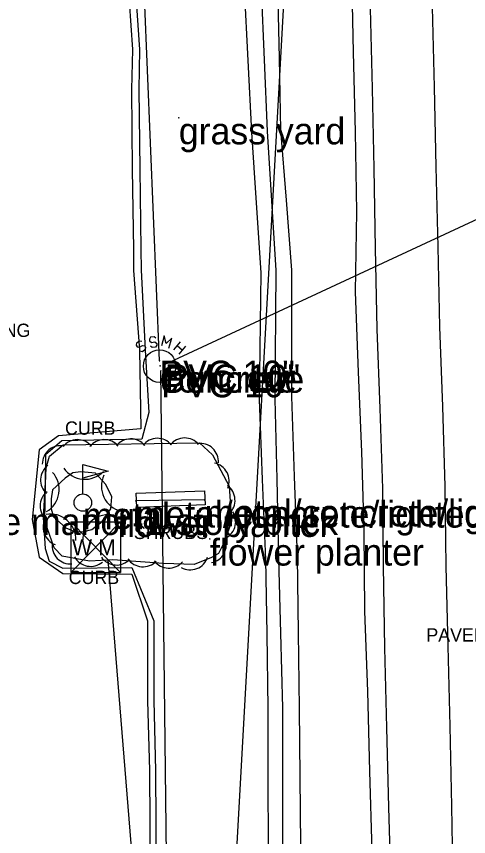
# Model space of a CAD drawing. Extents: x 1802180 to 1804859, y 572524 to 575172.
# Drawn here: x 1803444.8 to 1803529.6, y 574596.9 to 574750.8 of the extents above; entities that cross this region are included whole.
import ezdxf

# ---------------------------------------------------------------- set-up
doc = ezdxf.new("R2010")
doc.units = 0
for name, color, linetype in [('EX_EDGE_PAVEMENT', 7, 'Continuous'), ('EX_SHOULDER', 7, 'Continuous'), ('S_BASELINE', 7, 'Continuous'), ('S_CURB', 7, 'Continuous'), ('S_CURB_ANNOT', 7, 'Continuous'), ('S_DITCHLINE', 7, 'Continuous'), ('S_FLAG_POLE', 7, 'Continuous'), ('S_FLAG_POLE_ANNOT', 7, 'Continuous'), ('S_MANHOLE_ANNOT', 7, 'Continuous'), ('S_MSC_PT_SYM', 7, 'Continuous'), ('S_PARKING', 7, 'Continuous'), ('S_PARKING_ANNOT', 7, 'Continuous'), ('S_PAVEMENT_CROWN', 7, 'Continuous'), ('S_SANITARY_SEWER', 7, 'Continuous'), ('S_SANITARY_SEWER_ANNOT', 7, 'Continuous'), ('S_SHOULDER_ANNOT', 7, 'Continuous'), ('S_SIGN', 7, 'Continuous'), ('S_SIGN_ANNOT', 7, 'Continuous'), ('S_SURVEY_TEXT_ANNOT', 7, 'Continuous'), ('S_TREE', 7, 'Continuous'), ('S_TREE_ANNOT', 7, 'Continuous'), ('S_UTL_PT_SYM', 7, 'Continuous'), ('S_WATER_UTILITIES', 7, 'Continuous')]:
    doc.layers.add(name, color=color, linetype=linetype)

msp = doc.modelspace()

# ---------------------------------------------------------------- linework, layer by layer
at = {"layer": 'EX_EDGE_PAVEMENT'}
msp.add_lwpolyline([(1803511.15, 574752.25), (1803511.51, 574737.25), (1803511.85, 574722.28), (1803512.06, 574707.28), (1803512.41, 574692.1), (1803512.98, 574677.21), (1803513.44, 574662.21), (1803513.59, 574647.61), (1803513.85, 574632.28), (1803514.23, 574617.28), (1803514.59, 574602.41), (1803515.02, 574587.41), (1803515.25, 574572.41), (1803515.5, 574557.21), (1803515.92, 574542.31), (1803516.28, 574527.32), (1803516.63, 574512.39), (1803516.94, 574497.47), (1803517.26, 574482.47), (1803517.51, 574467.47)], dxfattribs=at)
at = {"layer": 'EX_SHOULDER'}
msp.add_lwpolyline([(1803513.3, 574459.21), (1803513.14, 574474.16), (1803512.83, 574489.15), (1803512.51, 574504.15), (1803513.08, 574519.16), (1803512.55, 574534.14), (1803512.14, 574549.14), (1803512, 574564.12), (1803511.96, 574579.17), (1803511.52, 574594.12), (1803511.07, 574609.12), (1803510.69, 574624.12), (1803510.14, 574639.14), (1803510.02, 574654.22), (1803509.58, 574669.09), (1803508.98, 574684.03), (1803508.41, 574699.09), (1803508.62, 574714.13), (1803508.42, 574729.1), (1803508.04, 574744.09), (1803507.71, 574759.1)], dxfattribs=at)
at = {"layer": 'S_BASELINE'}
msp.add_line((1803445.92, 573868.28), (1803500.45, 574852.59), dxfattribs=at)
at = {"layer": 'S_CURB'}
msp.add_lwpolyline([(1803467.27, 574753.7), (1803467.89, 574744.56), (1803467.75, 574737.06), (1803467.92, 574722.11), (1803468.12, 574707.11), (1803468.17, 574703.2), (1803468.95, 574688.18), (1803469.61, 574676.46), (1803468.29, 574671.46), (1803453.29, 574671.14), (1803450.27, 574668.52), (1803450.2, 574663.33), (1803449.82, 574656.78), (1803450.16, 574650.94), (1803450.92, 574648.56), (1803453.5, 574647.22), (1803466.47, 574647.34), (1803470.55, 574637.34), (1803470.57, 574622.37), (1803470.89, 574609.28), (1803470.96, 574599.35), (1803470.98, 574589.91)], dxfattribs=at)
at = {"layer": 'S_DITCHLINE'}
for points in [[(1803490.07, 574794.16), (1803489.66, 574780.03), (1803490.7, 574755.99), (1803491.27, 574742.62), (1803491.83, 574729.26), (1803492.65, 574716.19), (1803493.48, 574703.12), (1803493.27, 574678.93), (1803493.61, 574663.96), (1803493.94, 574648.99), (1803494.34, 574635.02), (1803494.73, 574621.05), (1803494.72, 574607.79), (1803494.71, 574594.54), (1803495.49, 574581.95), (1803496.28, 574569.36), (1803495.67, 574551.97), (1803495.95, 574537.6), (1803495.58, 574518.76), (1803495.69, 574501.1), (1803495.36, 574490.9), (1803494.55, 574477.41), (1803495.42, 574468.77), (1803496.15, 574468.87)], [(1803490.07, 574794.16), (1803491.29, 574793.32), (1803491.77, 574780.2), (1803493.77, 574756.45), (1803494.07, 574742.95), (1803494.36, 574729.45), (1803495.37, 574716.3), (1803496.38, 574703.14), (1803496.39, 574679.47), (1803496.92, 574664.43), (1803497.45, 574649.38), (1803497.65, 574635.15), (1803497.85, 574620.92), (1803497.95, 574608.06), (1803498.05, 574595.2), (1803498.74, 574582.27), (1803499.43, 574569.34), (1803499.04, 574551.94), (1803499.25, 574537.64), (1803498.31, 574518.86), (1803498.17, 574501.26), (1803497.39, 574490.99), (1803496.83, 574477.44), (1803496.15, 574468.87)], [(1803487.53, 574756.11), (1803488.21, 574742.54), (1803488.9, 574728.98), (1803489.77, 574715.83), (1803490.65, 574702.69), (1803490.32, 574678.88), (1803490.92, 574663.88), (1803491.52, 574648.88), (1803491.74, 574634.91), (1803491.96, 574620.93), (1803491.97, 574607.92), (1803491.99, 574594.91), (1803492.03, 574582.33), (1803492.07, 574569.76), (1803492.72, 574552.46), (1803493.14, 574537.68), (1803492.47, 574519.03), (1803493.27, 574501.14), (1803493.74, 574490.94), (1803492.85, 574477.56), (1803494.06, 574470.25), (1803495.42, 574468.77)]]:
    msp.add_lwpolyline(points, dxfattribs=at)
at = {"layer": 'S_FLAG_POLE'}
for p, q in [((1803457.25, 574661.16), (1803457.25, 574666.7)), ((1803457.25, 574666.7), (1803462.01, 574665.43)), ((1803462.01, 574665.43), (1803457.25, 574664.15))]:
    msp.add_line(p, q, dxfattribs=at)
msp.add_circle((1803457.25, 574659.54), 1.63, dxfattribs=at)
at = {"layer": 'S_MSC_PT_SYM'}
for points in [[(1803475.26, 574731.78), (1803475.26, 574731.83), (1803475.26, 574731.78), (1803475.21, 574731.78), (1803475.26, 574731.78), (1803475.26, 574731.73), (1803475.26, 574731.78), (1803475.31, 574731.78)], [(1803467.16, 574659.85), (1803467.16, 574659.9), (1803467.16, 574659.85), (1803467.11, 574659.85), (1803467.16, 574659.85), (1803467.16, 574659.8), (1803467.16, 574659.85), (1803467.21, 574659.85)], [(1803480.08, 574660.09), (1803480.08, 574660.14), (1803480.08, 574660.09), (1803480.03, 574660.09), (1803480.08, 574660.09), (1803480.08, 574660.04), (1803480.08, 574660.09), (1803480.13, 574660.09)], [(1803463.71, 574658.1), (1803463.71, 574658.15), (1803463.71, 574658.1), (1803463.66, 574658.1), (1803463.71, 574658.1), (1803463.71, 574658.05), (1803463.71, 574658.1), (1803463.76, 574658.1)], [(1803481.09, 574652.72), (1803481.09, 574652.77), (1803481.09, 574652.72), (1803481.04, 574652.72), (1803481.09, 574652.72), (1803481.09, 574652.67), (1803481.09, 574652.72), (1803481.14, 574652.72)]]:
    msp.add_lwpolyline(points, dxfattribs=at)
at = {"layer": 'S_PARKING'}
msp.add_lwpolyline([(1803465.97, 574753.62), (1803466.55, 574744.6), (1803466.36, 574737.09), (1803466.52, 574722.09), (1803466.73, 574707.09), (1803466.78, 574703.1), (1803467.85, 574688.16), (1803468.11, 574673.42), (1803452.66, 574672.05), (1803449.03, 574669.45), (1803447.73, 574656.4), (1803449.04, 574649.33), (1803453.47, 574646.26), (1803466.43, 574646.12), (1803469.38, 574637.34), (1803469.4, 574622.34), (1803469.77, 574609.24), (1803469.84, 574599.34), (1803469.86, 574589.91)], dxfattribs=at)
msp.add_lwpolyline([(1803465.97, 574753.62), (1803466.55, 574744.6), (1803466.36, 574737.09), (1803466.52, 574722.09), (1803466.73, 574707.09), (1803466.78, 574703.1), (1803467.85, 574688.16), (1803468.11, 574673.42), (1803452.66, 574672.05), (1803449.03, 574669.45), (1803447.73, 574656.4), (1803449.04, 574649.33), (1803453.47, 574646.26), (1803466.43, 574646.12), (1803469.38, 574637.34), (1803469.4, 574622.34), (1803469.77, 574609.24), (1803469.84, 574599.34), (1803469.86, 574589.91)], dxfattribs=at)
at = {"layer": 'S_PAVEMENT_CROWN'}
msp.add_lwpolyline([(1803522.78, 574752.53), (1803523.15, 574737.54), (1803523.48, 574722.54), (1803523.82, 574707.54), (1803524.16, 574692.55), (1803524.71, 574677.56), (1803525.16, 574662.57), (1803525.35, 574647.57), (1803525.71, 574632.58), (1803526.09, 574617.58), (1803526.43, 574602.58), (1803526.65, 574587.59), (1803526.88, 574572.59), (1803527.34, 574557.6), (1803527.76, 574542.6), (1803528.13, 574527.61), (1803528.41, 574512.61), (1803528.68, 574497.61), (1803528.87, 574482.61), (1803529.05, 574467.61)], dxfattribs=at)
at = {"layer": 'S_SANITARY_SEWER'}
for p, q in [((1803471.62, 574686.18), (1803464.18, 574867.1)), ((1803472.59, 574685.48), (1803580.89, 574735.83)), ((1803467.87, 574689.85), (1803467.33, 574689.46)), ((1803468.3, 574689.77), (1803467.87, 574689.85)), ((1803467.33, 574689.46), (1803467.25, 574689.07)), ((1803467.25, 574689.07), (1803467.44, 574688.8)), ((1803467.44, 574688.8), (1803467.87, 574688.69)), ((1803467.87, 574688.69), (1803468.41, 574689.03)), ((1803468.41, 574689.03), (1803468.88, 574688.96)), ((1803468.88, 574688.96), (1803469.03, 574688.69)), ((1803469.03, 574688.69), (1803468.95, 574688.26)), ((1803474.3, 574688.22), (1803475.54, 574689.69)), ((1803474.96, 574689), (1803475.93, 574688.18)), ((1803476.51, 574688.88), (1803475.27, 574687.41)), ((1803468.41, 574687.87), (1803468.02, 574687.95)), ((1803468.95, 574688.26), (1803468.41, 574687.87)), ((1803476.11, 574323.57), (1803471.91, 574684.3))]:
    msp.add_line(p, q, dxfattribs=at)
for points in [[(1803470.97, 574690.39), (1803470.62, 574690.66), (1803469.96, 574690.58), (1803469.73, 574690.24), (1803469.77, 574689.93), (1803470.12, 574689.62), (1803470.74, 574689.73), (1803471.12, 574689.42), (1803471.16, 574689.11), (1803470.89, 574688.72), (1803470.27, 574688.65), (1803469.92, 574688.92)], [(1803473.41, 574688.53), (1803473.95, 574690.39), (1803472.91, 574689.38), (1803472.52, 574690.82), (1803471.98, 574688.96)]]:
    msp.add_lwpolyline(points, dxfattribs=at)
msp.add_circle((1803471.65, 574685.16), 3.05, dxfattribs=at)
at = {"layer": 'S_SIGN'}
msp.add_line((1803480.08, 574660.09), (1803467.16, 574659.85), dxfattribs=at)
msp.add_lwpolyline([(1803467.24, 574661.29), (1803480.1, 574661.75), (1803480.21, 574659.14), (1803467.39, 574658.63), (1803467.24, 574661.29)], dxfattribs=at)
at = {"layer": 'S_TREE'}
for points in [[(1803453.55, 574670.4), (1803479.13, 574670.77), (1803481.56, 574668.5), (1803484.71, 574662.64), (1803485.12, 574656.05), (1803483.85, 574652.17), (1803483.21, 574651.01), (1803482.67, 574650.02), (1803481.38, 574649.23), (1803478.16, 574647.96), (1803472.38, 574648.13), (1803462.87, 574648.83), (1803458.48, 574648.54), (1803453.35, 574649.5), (1803451.84, 574651.05), (1803450.12, 574656.07), (1803450.22, 574663.14), (1803450.37, 574666.07), (1803450.97, 574668.28), (1803453.55, 574670.4)], [(1803453.95, 574664.11), (1803451.55, 574661.96), (1803451.29, 574660.26), (1803451.33, 574658.36), (1803451.75, 574656.86), (1803454.07, 574654.84), (1803455.57, 574654.16), (1803457.23, 574654.04), (1803458.96, 574654.49), (1803460.89, 574656.03), (1803462.51, 574658.35), (1803462.67, 574660.62), (1803461.57, 574662.93), (1803459.62, 574665.09), (1803456.87, 574665.32), (1803455.37, 574665.11), (1803453.95, 574664.11)]]:
    msp.add_lwpolyline(points, dxfattribs=at)
for centre, radius, start, end in [((1803456.24, 574667.93), 3.43, 40.0263, 141.6232), ((1803461.26, 574667.94), 3.43, 40.0263, 141.6232), ((1803466.23, 574668.08), 3.43, 40.0263, 141.6232), ((1803471.23, 574668.18), 3.43, 40.0263, 141.6232), ((1803476.35, 574668.25), 3.43, 40.0263, 141.6232), ((1803453.07, 574666.8), 3.43, 78.6989, 180.2959), ((1803479.25, 574667.23), 3.43, 356.154, 97.7509), ((1803481.28, 574663.58), 3.43, 337.4974, 79.0943), ((1803452.73, 574663.78), 3.43, 126.1663, 227.7632), ((1803448, 574662), 4.81, 300.4034, 42.0003), ((1803457.63, 574668.73), 4.81, 214.5545, 316.1514), ((1803465.55, 574662.63), 4.81, 154.6948, 256.2917), ((1803482.37, 574659.97), 3.43, 312.739, 54.3359), ((1803452.66, 574658.89), 3.43, 128.392, 229.9889), ((1803482.49, 574655.96), 3.43, 291.0588, 32.6557), ((1803453.24, 574654.9), 3.43, 148.1606, 249.7575), ((1803451.15, 574652.59), 4.81, 358.07, 99.6669), ((1803462.05, 574652.46), 4.81, 77.7839, 179.3808), ((1803480.74, 574651.65), 3.43, 280.6071, 22.204), ((1803454.92, 574651.47), 3.43, 173.2207, 274.8176), ((1803458.71, 574651.01), 3.43, 208.6222, 310.2191), ((1803463.54, 574651.26), 3.43, 215.0011, 316.598), ((1803468.52, 574650.93), 3.43, 215.0011, 316.598), ((1803473.38, 574650.68), 3.43, 217.4723, 319.0692), ((1803477.39, 574650.35), 3.43, 240.7733, 342.3702)]:
    msp.add_arc(centre, radius, start, end, dxfattribs=at)
at = {"layer": 'S_UTL_PT_SYM'}
for points in [[(1803471.62, 574686.18), (1803471.62, 574686.23), (1803471.62, 574686.18), (1803471.57, 574686.18), (1803471.62, 574686.18), (1803471.62, 574686.13), (1803471.62, 574686.18), (1803471.67, 574686.18)], [(1803471.77, 574685.2), (1803471.77, 574685.25), (1803471.77, 574685.2), (1803471.72, 574685.2), (1803471.77, 574685.2), (1803471.77, 574685.15), (1803471.77, 574685.2), (1803471.82, 574685.2)], [(1803472.59, 574685.48), (1803472.59, 574685.53), (1803472.59, 574685.48), (1803472.54, 574685.48), (1803472.59, 574685.48), (1803472.59, 574685.43), (1803472.59, 574685.48), (1803472.64, 574685.48)], [(1803471.91, 574684.3), (1803471.91, 574684.35), (1803471.91, 574684.3), (1803471.86, 574684.3), (1803471.91, 574684.3), (1803471.91, 574684.25), (1803471.91, 574684.3), (1803471.96, 574684.3)], [(1803462, 574648.79), (1803462, 574648.84), (1803462, 574648.79), (1803461.95, 574648.79), (1803462, 574648.79), (1803462, 574648.74), (1803462, 574648.79), (1803462.05, 574648.79)]]:
    msp.add_lwpolyline(points, dxfattribs=at)
at = {"layer": 'S_WATER_UTILITIES'}
for p, q in [((1803455.01, 574655.91), (1803464.34, 574655.91)), ((1803455.01, 574655.91), (1803455.01, 574646.41)), ((1803455.01, 574655.91), (1803464.34, 574646.41)), ((1803464.34, 574655.91), (1803455.01, 574646.41)), ((1803464.34, 574655.91), (1803464.34, 574646.41)), ((1803481.26, 574410.73), (1803462, 574648.79)), ((1803455.01, 574646.41), (1803464.34, 574646.41))]:
    msp.add_line(p, q, dxfattribs=at)

# ---------------------------------------------------------------- texts
at = {"layer": 'S_CURB_ANNOT'}
for p in [(1803453.9, 574672.28), (1803454.59, 574644.26)]:
    msp.add_text('CURB', height=2.5, dxfattribs=at).set_placement(p)
at = {"layer": 'S_FLAG_POLE_ANNOT'}
msp.add_text('metal ', height=5, dxfattribs=at).set_placement((1803457.25, 574654.54))
at = {"layer": 'S_MANHOLE_ANNOT'}
msp.add_text('concrete   ', height=5, dxfattribs=at).set_placement((1803471.77, 574680.2))
at = {"layer": 'S_PARKING_ANNOT'}
msp.add_text('CONC PARKING', height=2.5, dxfattribs=at).set_placement((1803421.59, 574690.63))
at = {"layer": 'S_SANITARY_SEWER_ANNOT'}
for s, p in [('Concrete ', (1803471.65, 574680.16)), ('PVC 10" ', (1803471.62, 574681.18)), ('PVC 10" ', (1803472.59, 574680.48)), ('PVC 10" ', (1803471.91, 574679.3))]:
    msp.add_text(s, height=5, dxfattribs=at).set_placement(p)
at = {"layer": 'S_SHOULDER_ANNOT'}
msp.add_text('PAVED SHOULDER', height=2.5, dxfattribs=at).set_placement((1803521.69, 574633.46))
at = {"layer": 'S_SIGN_ANNOT'}
for s, p in [('metal/concrete/lighted monette manor ', (1803467.16, 574654.85)), ('metal/concrete/lighted monette manor', (1803480.08, 574655.09))]:
    msp.add_text(s, height=5, dxfattribs=at).set_placement(p)
at = {"layer": 'S_SURVEY_TEXT_ANNOT'}
for s, p in [('grass yard ', (1803475.26, 574726.78)), ('monette manor-1-story brick ', (1803421.52, 574653.47)), ('flower planter ', (1803463.71, 574653.1)), ('flower planter ', (1803481.09, 574647.72))]:
    msp.add_text(s, height=5, dxfattribs=at).set_placement(p)
at = {"layer": 'S_TREE_ANNOT'}
msp.add_text('SHRUBS', height=2.5, dxfattribs=at).set_placement((1803466.82, 574652.71))
msp.add_text('SHRUBS', height=2.5, dxfattribs=at).set_placement((1803466.82, 574652.71))
at = {"layer": 'S_WATER_UTILITIES'}
msp.add_text('W M', height=3, rotation=360, dxfattribs=at).set_placement((1803455.21, 574649.67))

doc.saveas('drawing.dxf')
